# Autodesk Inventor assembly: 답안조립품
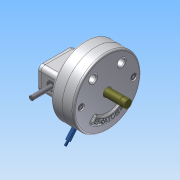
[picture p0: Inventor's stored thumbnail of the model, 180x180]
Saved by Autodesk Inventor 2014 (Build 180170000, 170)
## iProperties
Created: 2015-04
Part Number: 답안조립품
Document SubType Name: Assembly
Designer: Administrator
Mass: 3964.99 g
Surface Area: 3333.69 cm^2
Volume: 1140.85 cm^3
Density: 3.47547 g/cm^3
Author: Administrator
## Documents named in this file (15)
- C:\Documents and Settings\Administrator\바탕 화면\350406V1038\350406V1038\답안조립품.iam
- C:\Documents and Settings\Administrator\바탕 화면\350406V1038\350406V1038\본체.ipt
- C:\Documents and Settings\Administrator\바탕 화면\350406V1038\350406V1038\커버.ipt
- C:\Documents and Settings\Administrator\바탕 화면\350406V1038\350406V1038\커버2.ipt
- C:\Documents and Settings\Administrator\바탕 화면\350406V1038\350406V1038\M 5 x 12.ipt
- C:\Documents and Settings\Administrator\바탕 화면\350406V1038\350406V1038\M 10 x 35.ipt
- C:\Documents and Settings\Administrator\바탕 화면\350406V1038\350406V1038\가변스프링.ipt
- C:\Documents and Settings\Administrator\바탕 화면\350406V1038\350406V1038\슬라이더3.ipt
- C:\Documents and Settings\Administrator\바탕 화면\350406V1038\350406V1038\부시.ipt
- C:\Documents and Settings\Administrator\바탕 화면\350406V1038\350406V1038\축.ipt
- C:\Documents and Settings\Administrator\바탕 화면\350406V1038\350406V1038\멈춤링.ipt
- C:\Documents and Settings\Administrator\바탕 화면\350406V1038\350406V1038\베어링62_22.ipt
- C:\Documents and Settings\Administrator\바탕 화면\350406V1038\350406V1038\슬라이더2.ipt
- C:\Documents and Settings\Administrator\바탕 화면\350406V1038\350406V1038\슬라이더.ipt
- C:\Documents and Settings\Administrator\바탕 화면\350406V1038\350406V1038\평행핀.ipt
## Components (6 placed, 4 different names)
1. M 5 x 12:1
2. M 5 x 12:2
3. 가변스프링:1
4. KS B 1320 B B 5 x  20:1
5. M 10 x 35:1
6. M 10 x 35:2
